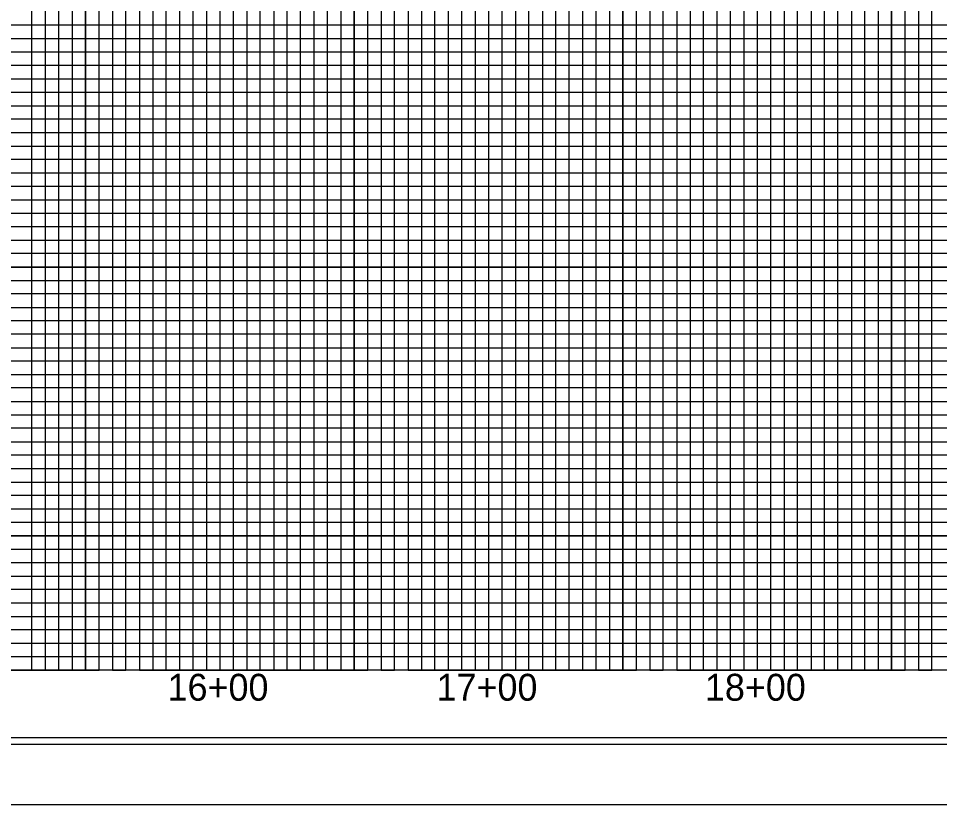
# Model space of a CAD drawing. Extents: x 574125 to 576234, y -56630 to -55530.
# Drawn here: x 575081.8 to 575424.7, y -56629.8 to -56337.3 of the extents above; entities that cross this region are included whole.
import ezdxf

# ---------------------------------------------------------------- set-up
doc = ezdxf.new("R2010")
doc.units = 0
for name, color, linetype in [('Exist Vertical Profile Horizontal Axis Label Major', 7, 'Continuous'), ('Sheet DOT Grid CELL', 7, 'Continuous'), ('Sheet Plot Border Inside CELL', 7, 'Continuous'), ('Sheet Plot Border Outside CELL', 7, 'Continuous'), ('Sheet Profile CELL', 7, 'Continuous'), ('Sheet Profile Grid Major CELL', 7, 'Continuous'), ('Sheet Profile Grid Middle CELL', 7, 'Continuous'), ('Sheet Profile Grid Minor CELL', 7, 'Continuous')]:
    doc.layers.add(name, color=color, linetype=linetype)

msp = doc.modelspace()

# ---------------------------------------------------------------- linework, layer by layer
at = {"layer": 'Sheet DOT Grid CELL'}
for p, q in [((575106.81, -55554.85), (575106.81, -56579.85)), ((575156.81, -55554.85), (575156.81, -56579.85)), ((575206.81, -55554.85), (575206.81, -56579.85)), ((575256.81, -55554.85), (575256.81, -56579.85)), ((575306.81, -55554.85), (575306.81, -56579.85)), ((575356.81, -55554.85), (575356.81, -56579.85)), ((575406.81, -55554.85), (575406.81, -56579.85)), ((574506.81, -56379.85), (576006.81, -56379.85)), ((574506.81, -56429.85), (576006.81, -56429.85)), ((574506.81, -56479.85), (576006.81, -56479.85)), ((574506.81, -56529.85), (576006.81, -56529.85))]:
    msp.add_line(p, q, dxfattribs=at)
at = {"layer": 'Sheet Plot Border Inside CELL'}
msp.add_lwpolyline([(576019.31, -55552.3), (574352.81, -55552.3), (574352.81, -56607.4), (576019.31, -56607.4)], close=True, dxfattribs=at)
at = {"layer": 'Sheet Plot Border Outside CELL'}
msp.add_lwpolyline([(576023.81, -55529.85), (574339.81, -55529.85), (574339.81, -56629.85), (576023.81, -56629.85)], close=True, dxfattribs=at)
at = {"layer": 'Sheet Profile CELL'}
for p, q in [((576006.81, -56579.85), (574506.81, -56579.85)), ((574339.81, -56629.85), (576023.81, -56629.85))]:
    msp.add_line(p, q, dxfattribs=at)
msp.add_lwpolyline([(576006.81, -55554.85), (574506.81, -55554.85), (574506.81, -56604.85), (576006.81, -56604.85)], close=True, dxfattribs=at)
at = {"layer": 'Sheet Profile Grid Major CELL'}
for points in [[(575056.81, -56579.85), (575106.81, -56579.85), (575106.81, -55554.85)], [(575156.81, -55554.85), (575156.81, -56579.85), (575206.81, -56579.85), (575206.81, -55554.85)], [(575256.81, -55554.85), (575256.81, -56579.85), (575306.81, -56579.85), (575306.81, -55554.85)], [(575356.81, -55554.85), (575356.81, -56579.85), (575406.81, -56579.85), (575406.81, -55554.85)], [(576006.81, -56429.85), (574506.81, -56429.85), (574506.81, -56379.85), (576006.81, -56379.85)], [(576006.81, -56529.85), (574506.81, -56529.85), (574506.81, -56479.85), (576006.81, -56479.85)]]:
    msp.add_lwpolyline(points, dxfattribs=at)
at = {"layer": 'Sheet Profile Grid Middle CELL'}
for points in [[(575131.81, -55554.85), (575131.81, -56579.85), (575181.81, -56579.85), (575181.81, -55554.85)], [(575231.81, -55554.85), (575231.81, -56579.85), (575281.81, -56579.85), (575281.81, -55554.85)], [(575331.81, -55554.85), (575331.81, -56579.85), (575381.81, -56579.85), (575381.81, -55554.85)], [(576006.81, -56354.85), (574506.81, -56354.85), (574506.81, -56404.85), (576006.81, -56404.85)], [(576006.81, -56454.85), (574506.81, -56454.85), (574506.81, -56504.85), (576006.81, -56504.85)], [(576006.81, -56554.85), (574506.81, -56554.85)]]:
    msp.add_lwpolyline(points, dxfattribs=at)
at = {"layer": 'Sheet Profile Grid Minor CELL'}
for points in [[(575086.81, -56579.85), (575086.81, -55554.85)], [(575091.81, -55554.85), (575091.81, -56579.85), (575096.81, -56579.85), (575096.81, -55554.85)], [(575101.81, -55554.85), (575101.81, -56579.85), (575111.81, -56579.85), (575111.81, -55554.85)], [(575116.81, -55554.85), (575116.81, -56579.85), (575116.81, -56579.85), (575121.81, -56579.85), (575121.81, -55554.85)], [(575126.81, -55554.85), (575126.81, -56579.85), (575136.81, -56579.85), (575136.81, -55554.85)], [(575141.81, -55554.85), (575141.81, -56579.85), (575146.81, -56579.85), (575146.81, -55554.85)], [(575151.81, -55554.85), (575151.81, -56579.85), (575161.81, -56579.85), (575161.81, -55554.85)], [(575166.81, -55554.85), (575166.81, -56579.85), (575171.81, -56579.85), (575171.81, -55554.85)], [(575176.81, -55554.85), (575176.81, -56579.85), (575186.81, -56579.85), (575186.81, -55554.85)], [(575191.81, -55554.85), (575191.81, -56579.85), (575196.81, -56579.85), (575196.81, -55554.85)], [(575201.81, -55554.85), (575201.81, -56579.85), (575211.81, -56579.85), (575211.81, -55554.85)], [(575216.81, -55554.85), (575216.81, -56579.85), (575221.81, -56579.85), (575221.81, -55554.85)], [(575226.81, -55554.85), (575226.81, -56579.85), (575236.81, -56579.85), (575236.81, -55554.85)], [(575241.81, -55554.85), (575241.81, -56579.85), (575246.81, -56579.85), (575246.81, -55554.85)], [(575251.81, -55554.85), (575251.81, -56579.85), (575261.81, -56579.85), (575261.81, -55554.85)], [(575266.81, -55554.85), (575266.81, -56579.85)], [(575266.81, -56579.85), (575271.81, -56579.85), (575271.81, -55555.45)], [(575276.81, -55555.45), (575276.81, -56579.85), (575286.81, -56579.85), (575286.81, -55554.85)], [(575291.81, -55554.85), (575291.81, -56579.85), (575296.81, -56579.85), (575296.81, -55554.85)], [(575301.81, -55554.85), (575301.81, -56579.85), (575311.81, -56579.85), (575311.81, -55554.85)], [(575316.81, -55554.85), (575316.81, -56579.85), (575321.81, -56579.85), (575321.81, -55554.85)], [(575326.81, -55554.85), (575326.81, -56579.85), (575336.81, -56579.85), (575336.81, -55554.85)], [(575341.81, -55554.85), (575341.81, -56579.85), (575346.81, -56579.85), (575346.81, -55554.85)], [(575351.81, -55554.85), (575351.81, -56579.85), (575361.81, -56579.85), (575361.81, -55554.85)], [(575366.81, -55554.85), (575366.81, -56579.85), (575371.81, -56579.85), (575371.81, -55554.85)], [(575376.81, -55554.85), (575376.81, -56579.85), (575386.81, -56579.85), (575386.81, -55554.85)], [(575391.81, -55554.85), (575391.81, -56579.85), (575396.81, -56579.85), (575396.81, -55554.85)], [(575401.81, -55554.85), (575401.81, -56579.85), (575411.81, -56579.85), (575411.81, -55554.85)], [(575416.81, -55554.85), (575416.81, -56579.85), (575421.81, -56579.85), (575421.81, -55554.85)], [(575956.81, -56339.85), (574556.81, -56339.85), (574556.81, -56344.85), (575956.81, -56344.85)], [(575956.81, -56349.85), (574556.81, -56349.85), (574556.81, -56359.85), (575956.81, -56359.85)], [(575956.81, -56364.85), (574556.81, -56364.85), (574556.81, -56369.85), (575956.81, -56369.85)], [(575956.81, -56374.85), (574556.81, -56374.85)], [(574556.81, -56384.85), (575956.81, -56384.85)], [(575956.81, -56389.85), (574556.81, -56389.85), (574556.81, -56394.85), (575956.81, -56394.85)], [(575956.81, -56399.85), (574556.81, -56399.85)], [(574556.81, -56409.85), (575956.81, -56409.85)], [(575956.81, -56414.85), (574556.81, -56414.85), (574556.81, -56419.85), (575956.81, -56419.85)], [(575956.81, -56424.85), (574556.81, -56424.85), (574556.81, -56434.85), (575956.81, -56434.85)], [(575956.81, -56439.85), (574556.81, -56439.85), (574556.81, -56444.85), (575956.81, -56444.85)], [(575956.81, -56449.85), (574556.81, -56449.85), (574556.81, -56459.85), (575956.81, -56459.85)], [(575956.81, -56464.85), (574556.81, -56464.85), (574556.81, -56469.85), (575956.81, -56469.85)], [(575956.81, -56474.85), (574556.81, -56474.85), (574556.81, -56484.85), (575956.81, -56484.85)], [(575956.81, -56489.85), (574556.81, -56489.85), (574556.81, -56494.85), (575956.81, -56494.85)], [(575956.81, -56499.85), (574556.81, -56499.85), (574556.81, -56509.85), (575956.81, -56509.85)], [(575956.81, -56514.85), (574556.81, -56514.85), (574556.81, -56519.85), (575956.81, -56519.85)], [(575956.81, -56524.85), (574556.81, -56524.85), (574556.81, -56534.85), (575956.81, -56534.85)], [(575956.81, -56539.85), (574556.81, -56539.85), (574556.81, -56544.85), (575956.81, -56544.85)], [(575956.81, -56549.85), (574556.81, -56549.85), (574556.81, -56559.85), (575956.81, -56559.85)], [(575956.81, -56564.85), (574556.81, -56564.85), (574556.81, -56569.85), (575956.81, -56569.85)], [(575956.81, -56574.85), (574556.81, -56574.85)]]:
    msp.add_lwpolyline(points, dxfattribs=at)

# ---------------------------------------------------------------- texts
at = {"layer": 'Exist Vertical Profile Horizontal Axis Label Major'}
for s, p in [('16+00', (575137.31, -56591.2)), ('17+00', (575237.42, -56591.2)), ('18+00', (575337.31, -56591.2))]:
    msp.add_text(s, height=10, rotation=360, dxfattribs=at).set_placement(p)

doc.saveas('drawing.dxf')
